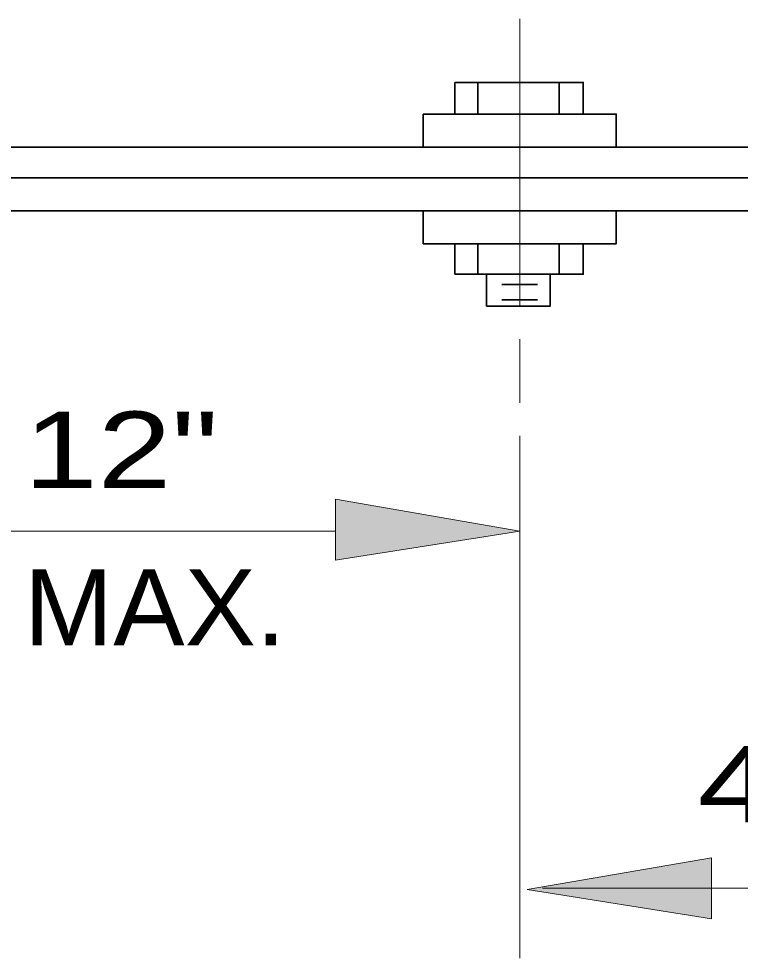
# Model space of a CAD drawing. Extents: x 5332.5 to 5339, y 1824.9 to 1835.1.
# Drawn here: x 5334.646 to 5335.213, y 1826.465 to 1827.204 of the extents above; entities that cross this region are included whole.
import ezdxf

# ---------------------------------------------------------------- set-up
doc = ezdxf.new("R2010")
doc.units = 0
doc.header["$LTSCALE"] = 0.024
for name, color, linetype, lineweight in [('1', 7, 'Continuous', 35), ('10', 7, 'Continuous', 13), ('12', 7, 'Continuous', 53)]:
    doc.layers.add(name, color=color, linetype=linetype, lineweight=lineweight)

msp = doc.modelspace()

# ---------------------------------------------------------------- hatches: boundary and pattern name
at = {"layer": '10'}
for points in [[(5334.895, 1826.778), (5334.895, 1826.826), (5335.04, 1826.801)], [(5334.895, 1826.778), (5334.895, 1826.826), (5335.04, 1826.801)], [(5334.895, 1826.778), (5334.895, 1826.826), (5335.04, 1826.801)], [(5334.895, 1826.778), (5334.895, 1826.826), (5335.04, 1826.801)], [(5334.895, 1826.778), (5334.895, 1826.826), (5335.04, 1826.801)], [(5334.895, 1826.778), (5334.895, 1826.826), (5335.04, 1826.801)], [(5334.895, 1826.778), (5334.895, 1826.826), (5335.04, 1826.801)], [(5334.895, 1826.778), (5334.895, 1826.826), (5335.04, 1826.801)], [(5334.895, 1826.778), (5334.895, 1826.826), (5335.04, 1826.801)], [(5334.895, 1826.778), (5334.895, 1826.826), (5335.04, 1826.801)], [(5334.895, 1826.778), (5334.895, 1826.826), (5335.04, 1826.801)], [(5335.191, 1826.496), (5335.191, 1826.544), (5335.046, 1826.519)]]:
    msp.add_hatch(color=256, dxfattribs=at).paths.add_polyline_path(points)

# ---------------------------------------------------------------- linework, layer by layer
at = {"layer": '1'}
for p, q in [((5334.989, 1827.154), (5335.04, 1827.154)), ((5334.989, 1827.129), (5334.989, 1827.154)), ((5334.989, 1827.154), (5335.04, 1827.154)), ((5334.989, 1827.129), (5334.989, 1827.154)), ((5334.989, 1827.154), (5335.04, 1827.154)), ((5334.989, 1827.129), (5334.989, 1827.154)), ((5334.989, 1827.154), (5335.04, 1827.154)), ((5334.989, 1827.129), (5334.989, 1827.154)), ((5334.989, 1827.154), (5335.04, 1827.154)), ((5334.989, 1827.129), (5334.989, 1827.154)), ((5334.989, 1827.154), (5335.04, 1827.154)), ((5334.989, 1827.129), (5334.989, 1827.154)), ((5334.989, 1827.154), (5335.04, 1827.154)), ((5334.989, 1827.129), (5334.989, 1827.154)), ((5334.989, 1827.154), (5335.04, 1827.154)), ((5334.989, 1827.129), (5334.989, 1827.154)), ((5334.989, 1827.154), (5335.04, 1827.154)), ((5334.989, 1827.129), (5334.989, 1827.154)), ((5334.989, 1827.154), (5335.04, 1827.154)), ((5334.989, 1827.129), (5334.989, 1827.154)), ((5334.989, 1827.154), (5335.04, 1827.154)), ((5334.989, 1827.129), (5334.989, 1827.154)), ((5335.007, 1827.154), (5335.007, 1827.129)), ((5335.007, 1827.154), (5335.007, 1827.129)), ((5335.007, 1827.154), (5335.007, 1827.129)), ((5335.007, 1827.154), (5335.007, 1827.129)), ((5335.007, 1827.154), (5335.007, 1827.129)), ((5335.007, 1827.154), (5335.007, 1827.129)), ((5335.007, 1827.154), (5335.007, 1827.129)), ((5335.007, 1827.154), (5335.007, 1827.129)), ((5335.007, 1827.154), (5335.007, 1827.129)), ((5335.007, 1827.154), (5335.007, 1827.129)), ((5335.007, 1827.154), (5335.007, 1827.129)), ((5335.071, 1827.154), (5335.071, 1827.129)), ((5335.071, 1827.154), (5335.071, 1827.129)), ((5335.071, 1827.154), (5335.071, 1827.129)), ((5335.071, 1827.154), (5335.071, 1827.129)), ((5335.071, 1827.154), (5335.071, 1827.129)), ((5335.071, 1827.154), (5335.071, 1827.129)), ((5335.071, 1827.154), (5335.071, 1827.129)), ((5335.071, 1827.154), (5335.071, 1827.129)), ((5335.071, 1827.154), (5335.071, 1827.129)), ((5335.071, 1827.154), (5335.071, 1827.129)), ((5335.071, 1827.154), (5335.071, 1827.129)), ((5335.071, 1827.154), (5335.071, 1827.129)), ((5335.071, 1827.154), (5335.071, 1827.129)), ((5334.964, 1827.129), (5335.04, 1827.129)), ((5334.964, 1827.103), (5334.964, 1827.129)), ((5334.964, 1827.129), (5335.04, 1827.129)), ((5334.964, 1827.103), (5334.964, 1827.129)), ((5334.964, 1827.129), (5335.04, 1827.129)), ((5334.964, 1827.103), (5334.964, 1827.129)), ((5334.964, 1827.129), (5335.04, 1827.129)), ((5334.964, 1827.103), (5334.964, 1827.129)), ((5334.964, 1827.129), (5335.04, 1827.129)), ((5334.964, 1827.103), (5334.964, 1827.129)), ((5334.964, 1827.129), (5335.04, 1827.129)), ((5334.964, 1827.103), (5334.964, 1827.129)), ((5334.964, 1827.129), (5335.04, 1827.129)), ((5334.964, 1827.103), (5334.964, 1827.129)), ((5334.964, 1827.129), (5335.04, 1827.129)), ((5334.964, 1827.103), (5334.964, 1827.129)), ((5334.964, 1827.129), (5335.04, 1827.129)), ((5334.964, 1827.103), (5334.964, 1827.129)), ((5334.964, 1827.129), (5335.04, 1827.129)), ((5334.964, 1827.103), (5334.964, 1827.129)), ((5334.964, 1827.129), (5335.04, 1827.129)), ((5334.964, 1827.103), (5334.964, 1827.129)), ((5337.53, 1827.103), (5333.857, 1827.103)), ((5334.26, 1827.079), (5335.492, 1827.079)), ((5334.26, 1827.079), (5335.492, 1827.079)), ((5334.26, 1827.079), (5335.492, 1827.079)), ((5334.26, 1827.079), (5335.492, 1827.079)), ((5334.26, 1827.079), (5335.492, 1827.079)), ((5334.26, 1827.079), (5335.492, 1827.079)), ((5334.26, 1827.079), (5335.492, 1827.079)), ((5334.26, 1827.079), (5335.492, 1827.079)), ((5334.26, 1827.079), (5335.492, 1827.079)), ((5334.26, 1827.079), (5335.492, 1827.079)), ((5334.26, 1827.079), (5335.492, 1827.079)), ((5334.26, 1827.079), (5335.492, 1827.079)), ((5334.26, 1827.079), (5335.492, 1827.079)), ((5334.964, 1827.053), (5334.964, 1827.027)), ((5334.964, 1827.053), (5334.964, 1827.027)), ((5334.964, 1827.053), (5334.964, 1827.027)), ((5334.964, 1827.053), (5334.964, 1827.027)), ((5334.964, 1827.053), (5334.964, 1827.027)), ((5334.964, 1827.053), (5334.964, 1827.027)), ((5334.964, 1827.053), (5334.964, 1827.027)), ((5334.964, 1827.053), (5334.964, 1827.027)), ((5334.964, 1827.053), (5334.964, 1827.027)), ((5334.964, 1827.053), (5334.964, 1827.027)), ((5334.964, 1827.053), (5334.964, 1827.027)), ((5334.964, 1827.053), (5334.964, 1827.027)), ((5334.964, 1827.053), (5334.964, 1827.027)), ((5334.964, 1827.027), (5335.04, 1827.027)), ((5334.964, 1827.027), (5335.04, 1827.027)), ((5334.964, 1827.027), (5335.04, 1827.027)), ((5334.964, 1827.027), (5335.04, 1827.027)), ((5334.964, 1827.027), (5335.04, 1827.027)), ((5334.964, 1827.027), (5335.04, 1827.027)), ((5334.964, 1827.027), (5335.04, 1827.027)), ((5334.964, 1827.027), (5335.04, 1827.027)), ((5334.964, 1827.027), (5335.04, 1827.027)), ((5334.964, 1827.027), (5335.04, 1827.027)), ((5334.964, 1827.027), (5335.04, 1827.027)), ((5334.964, 1827.027), (5335.04, 1827.027)), ((5334.964, 1827.027), (5335.04, 1827.027)), ((5334.989, 1827.027), (5334.989, 1827.003)), ((5334.989, 1827.027), (5334.989, 1827.003)), ((5334.989, 1827.027), (5334.989, 1827.003)), ((5334.989, 1827.027), (5334.989, 1827.003)), ((5334.989, 1827.027), (5334.989, 1827.003)), ((5334.989, 1827.027), (5334.989, 1827.003)), ((5334.989, 1827.027), (5334.989, 1827.003)), ((5334.989, 1827.027), (5334.989, 1827.003)), ((5334.989, 1827.027), (5334.989, 1827.003)), ((5334.989, 1827.027), (5334.989, 1827.003)), ((5334.989, 1827.027), (5334.989, 1827.003)), ((5334.989, 1827.027), (5334.989, 1827.003)), ((5334.989, 1827.027), (5334.989, 1827.003)), ((5335.007, 1827.003), (5335.007, 1827.027)), ((5335.007, 1827.003), (5335.007, 1827.027)), ((5335.007, 1827.003), (5335.007, 1827.027)), ((5335.007, 1827.003), (5335.007, 1827.027)), ((5335.007, 1827.003), (5335.007, 1827.027)), ((5335.007, 1827.003), (5335.007, 1827.027)), ((5335.007, 1827.003), (5335.007, 1827.027)), ((5335.007, 1827.003), (5335.007, 1827.027)), ((5335.007, 1827.003), (5335.007, 1827.027)), ((5335.007, 1827.003), (5335.007, 1827.027)), ((5335.007, 1827.003), (5335.007, 1827.027)), ((5335.007, 1827.003), (5335.007, 1827.027)), ((5335.007, 1827.003), (5335.007, 1827.027)), ((5335.071, 1827.003), (5335.071, 1827.027)), ((5335.071, 1827.003), (5335.071, 1827.027)), ((5335.071, 1827.003), (5335.071, 1827.027)), ((5335.071, 1827.003), (5335.071, 1827.027)), ((5335.071, 1827.003), (5335.071, 1827.027)), ((5335.071, 1827.003), (5335.071, 1827.027)), ((5335.071, 1827.003), (5335.071, 1827.027)), ((5335.071, 1827.003), (5335.071, 1827.027)), ((5335.071, 1827.003), (5335.071, 1827.027)), ((5335.071, 1827.003), (5335.071, 1827.027)), ((5335.071, 1827.003), (5335.071, 1827.027)), ((5335.071, 1827.003), (5335.071, 1827.027)), ((5335.071, 1827.003), (5335.071, 1827.027)), ((5334.989, 1827.003), (5335.04, 1827.003)), ((5334.989, 1827.003), (5335.04, 1827.003)), ((5334.989, 1827.003), (5335.04, 1827.003)), ((5334.989, 1827.003), (5335.04, 1827.003)), ((5334.989, 1827.003), (5335.04, 1827.003)), ((5334.989, 1827.003), (5335.04, 1827.003)), ((5334.989, 1827.003), (5335.04, 1827.003)), ((5334.989, 1827.003), (5335.04, 1827.003)), ((5334.989, 1827.003), (5335.04, 1827.003)), ((5334.989, 1827.003), (5335.04, 1827.003)), ((5334.989, 1827.003), (5335.04, 1827.003)), ((5334.989, 1827.003), (5335.04, 1827.003)), ((5334.989, 1827.003), (5335.04, 1827.003)), ((5335.014, 1827.003), (5335.014, 1826.978)), ((5335.014, 1827.003), (5335.014, 1826.978)), ((5335.014, 1827.003), (5335.014, 1826.978)), ((5335.014, 1827.003), (5335.014, 1826.978)), ((5335.014, 1827.003), (5335.014, 1826.978)), ((5335.014, 1827.003), (5335.014, 1826.978)), ((5335.014, 1827.003), (5335.014, 1826.978)), ((5335.014, 1827.003), (5335.014, 1826.978)), ((5335.014, 1827.003), (5335.014, 1826.978)), ((5335.014, 1827.003), (5335.014, 1826.978)), ((5335.014, 1827.003), (5335.014, 1826.978)), ((5335.014, 1827.003), (5335.014, 1826.978)), ((5335.014, 1827.003), (5335.014, 1826.978)), ((5335.026, 1826.995), (5335.054, 1826.995)), ((5335.026, 1826.995), (5335.054, 1826.995)), ((5335.026, 1826.995), (5335.054, 1826.995)), ((5335.026, 1826.995), (5335.054, 1826.995)), ((5335.026, 1826.995), (5335.054, 1826.995)), ((5335.026, 1826.995), (5335.054, 1826.995)), ((5335.026, 1826.995), (5335.054, 1826.995)), ((5335.026, 1826.995), (5335.054, 1826.995)), ((5335.026, 1826.995), (5335.054, 1826.995)), ((5335.026, 1826.995), (5335.054, 1826.995)), ((5335.026, 1826.995), (5335.054, 1826.995)), ((5335.026, 1826.995), (5335.054, 1826.995)), ((5335.026, 1826.995), (5335.054, 1826.995)), ((5335.014, 1826.978), (5335.04, 1826.978)), ((5335.014, 1826.978), (5335.04, 1826.978)), ((5335.014, 1826.978), (5335.04, 1826.978)), ((5335.014, 1826.978), (5335.04, 1826.978)), ((5335.014, 1826.978), (5335.04, 1826.978)), ((5335.014, 1826.978), (5335.04, 1826.978)), ((5335.014, 1826.978), (5335.04, 1826.978)), ((5335.014, 1826.978), (5335.04, 1826.978)), ((5335.014, 1826.978), (5335.04, 1826.978)), ((5335.014, 1826.978), (5335.04, 1826.978)), ((5335.014, 1826.978), (5335.04, 1826.978)), ((5335.014, 1826.978), (5335.04, 1826.978)), ((5335.014, 1826.978), (5335.04, 1826.978)), ((5335.026, 1826.983), (5335.054, 1826.983)), ((5335.026, 1826.983), (5335.054, 1826.983)), ((5335.026, 1826.983), (5335.054, 1826.983)), ((5335.026, 1826.983), (5335.054, 1826.983)), ((5335.026, 1826.983), (5335.054, 1826.983)), ((5335.026, 1826.983), (5335.054, 1826.983)), ((5335.026, 1826.983), (5335.054, 1826.983)), ((5335.026, 1826.983), (5335.054, 1826.983)), ((5335.026, 1826.983), (5335.054, 1826.983)), ((5335.026, 1826.983), (5335.054, 1826.983)), ((5335.026, 1826.983), (5335.054, 1826.983)), ((5335.026, 1826.983), (5335.054, 1826.983)), ((5335.026, 1826.983), (5335.054, 1826.983))]:
    msp.add_line(p, q, dxfattribs=at)
for points in [[(5335.09, 1827.129), (5335.09, 1827.154), (5335.04, 1827.154)], [(5335.09, 1827.129), (5335.09, 1827.154), (5335.04, 1827.154)], [(5335.09, 1827.129), (5335.09, 1827.154), (5335.04, 1827.154)], [(5335.09, 1827.129), (5335.09, 1827.154), (5335.04, 1827.154)], [(5335.09, 1827.129), (5335.09, 1827.154), (5335.04, 1827.154)], [(5335.09, 1827.129), (5335.09, 1827.154), (5335.04, 1827.154)], [(5335.09, 1827.129), (5335.09, 1827.154), (5335.04, 1827.154)], [(5335.09, 1827.129), (5335.09, 1827.154), (5335.04, 1827.154)], [(5335.09, 1827.129), (5335.09, 1827.154), (5335.04, 1827.154)], [(5335.09, 1827.129), (5335.09, 1827.154), (5335.04, 1827.154)], [(5335.09, 1827.129), (5335.09, 1827.154), (5335.04, 1827.154)], [(5335.09, 1827.129), (5335.09, 1827.154), (5335.04, 1827.154)], [(5335.09, 1827.129), (5335.09, 1827.154), (5335.04, 1827.154)], [(5335.116, 1827.103), (5335.116, 1827.129), (5335.04, 1827.129)], [(5335.116, 1827.103), (5335.116, 1827.129), (5335.04, 1827.129)], [(5335.116, 1827.103), (5335.116, 1827.129), (5335.04, 1827.129)], [(5335.116, 1827.103), (5335.116, 1827.129), (5335.04, 1827.129)], [(5335.116, 1827.103), (5335.116, 1827.129), (5335.04, 1827.129)], [(5335.116, 1827.103), (5335.116, 1827.129), (5335.04, 1827.129)], [(5335.116, 1827.103), (5335.116, 1827.129), (5335.04, 1827.129)], [(5335.116, 1827.103), (5335.116, 1827.129), (5335.04, 1827.129)], [(5335.116, 1827.103), (5335.116, 1827.129), (5335.04, 1827.129)], [(5335.116, 1827.103), (5335.116, 1827.129), (5335.04, 1827.129)], [(5335.116, 1827.103), (5335.116, 1827.129), (5335.04, 1827.129)], [(5335.116, 1827.103), (5335.116, 1827.129), (5335.04, 1827.129)], [(5335.116, 1827.103), (5335.116, 1827.129), (5335.04, 1827.129)], [(5337.53, 1827.103), (5333.857, 1827.103), (5333.857, 1827.079), (5334.26, 1827.079)], [(5337.53, 1827.103), (5333.857, 1827.103), (5333.857, 1827.079), (5334.26, 1827.079)], [(5337.53, 1827.103), (5333.857, 1827.103), (5333.857, 1827.079), (5334.26, 1827.079)], [(5337.53, 1827.103), (5333.857, 1827.103), (5333.857, 1827.079), (5334.26, 1827.079)], [(5337.53, 1827.103), (5333.857, 1827.103), (5333.857, 1827.079), (5334.26, 1827.079)], [(5337.53, 1827.103), (5333.857, 1827.103), (5333.857, 1827.079), (5334.26, 1827.079)], [(5337.53, 1827.103), (5333.857, 1827.103), (5333.857, 1827.079), (5334.26, 1827.079)], [(5337.53, 1827.103), (5333.857, 1827.103), (5333.857, 1827.079), (5334.26, 1827.079)], [(5337.53, 1827.103), (5333.857, 1827.103), (5333.857, 1827.079), (5334.26, 1827.079)], [(5337.53, 1827.103), (5333.857, 1827.103), (5333.857, 1827.079), (5334.26, 1827.079)], [(5337.53, 1827.103), (5333.857, 1827.103), (5333.857, 1827.079), (5334.26, 1827.079)], [(5337.53, 1827.103), (5333.857, 1827.103), (5333.857, 1827.079), (5334.26, 1827.079)], [(5337.53, 1827.103), (5333.857, 1827.103), (5333.857, 1827.079), (5334.26, 1827.079)], [(5334.26, 1827.079), (5334.26, 1827.053), (5335.465, 1827.053)], [(5334.26, 1827.079), (5334.26, 1827.053), (5335.465, 1827.053)], [(5334.26, 1827.079), (5334.26, 1827.053), (5335.465, 1827.053)], [(5334.26, 1827.079), (5334.26, 1827.053), (5335.465, 1827.053)], [(5334.26, 1827.079), (5334.26, 1827.053), (5335.465, 1827.053)], [(5334.26, 1827.079), (5334.26, 1827.053), (5335.465, 1827.053)], [(5334.26, 1827.079), (5334.26, 1827.053), (5335.465, 1827.053)], [(5334.26, 1827.079), (5334.26, 1827.053), (5335.465, 1827.053)], [(5334.26, 1827.079), (5334.26, 1827.053), (5335.465, 1827.053)], [(5334.26, 1827.079), (5334.26, 1827.053), (5335.465, 1827.053)], [(5334.26, 1827.079), (5334.26, 1827.053), (5335.465, 1827.053)], [(5334.26, 1827.079), (5334.26, 1827.053), (5335.465, 1827.053)], [(5334.26, 1827.079), (5334.26, 1827.053), (5335.465, 1827.053)], [(5335.116, 1827.053), (5335.116, 1827.027), (5335.04, 1827.027)], [(5335.116, 1827.053), (5335.116, 1827.027), (5335.04, 1827.027)], [(5335.116, 1827.053), (5335.116, 1827.027), (5335.04, 1827.027)], [(5335.116, 1827.053), (5335.116, 1827.027), (5335.04, 1827.027)], [(5335.116, 1827.053), (5335.116, 1827.027), (5335.04, 1827.027)], [(5335.116, 1827.053), (5335.116, 1827.027), (5335.04, 1827.027)], [(5335.116, 1827.053), (5335.116, 1827.027), (5335.04, 1827.027)], [(5335.116, 1827.053), (5335.116, 1827.027), (5335.04, 1827.027)], [(5335.116, 1827.053), (5335.116, 1827.027), (5335.04, 1827.027)], [(5335.116, 1827.053), (5335.116, 1827.027), (5335.04, 1827.027)], [(5335.116, 1827.053), (5335.116, 1827.027), (5335.04, 1827.027)], [(5335.116, 1827.053), (5335.116, 1827.027), (5335.04, 1827.027)], [(5335.116, 1827.053), (5335.116, 1827.027), (5335.04, 1827.027)], [(5335.09, 1827.027), (5335.09, 1827.003), (5335.04, 1827.003)], [(5335.09, 1827.027), (5335.09, 1827.003), (5335.04, 1827.003)], [(5335.09, 1827.027), (5335.09, 1827.003), (5335.04, 1827.003)], [(5335.09, 1827.027), (5335.09, 1827.003), (5335.04, 1827.003)], [(5335.09, 1827.027), (5335.09, 1827.003), (5335.04, 1827.003)], [(5335.09, 1827.027), (5335.09, 1827.003), (5335.04, 1827.003)], [(5335.09, 1827.027), (5335.09, 1827.003), (5335.04, 1827.003)], [(5335.09, 1827.027), (5335.09, 1827.003), (5335.04, 1827.003)], [(5335.09, 1827.027), (5335.09, 1827.003), (5335.04, 1827.003)], [(5335.09, 1827.027), (5335.09, 1827.003), (5335.04, 1827.003)], [(5335.09, 1827.027), (5335.09, 1827.003), (5335.04, 1827.003)], [(5335.09, 1827.027), (5335.09, 1827.003), (5335.04, 1827.003)], [(5335.09, 1827.027), (5335.09, 1827.003), (5335.04, 1827.003)], [(5335.064, 1827.003), (5335.064, 1826.978), (5335.04, 1826.978)], [(5335.064, 1827.003), (5335.064, 1826.978), (5335.04, 1826.978)], [(5335.064, 1827.003), (5335.064, 1826.978), (5335.04, 1826.978)], [(5335.064, 1827.003), (5335.064, 1826.978), (5335.04, 1826.978)], [(5335.064, 1827.003), (5335.064, 1826.978), (5335.04, 1826.978)], [(5335.064, 1827.003), (5335.064, 1826.978), (5335.04, 1826.978)], [(5335.064, 1827.003), (5335.064, 1826.978), (5335.04, 1826.978)], [(5335.064, 1827.003), (5335.064, 1826.978), (5335.04, 1826.978)], [(5335.064, 1827.003), (5335.064, 1826.978), (5335.04, 1826.978)], [(5335.064, 1827.003), (5335.064, 1826.978), (5335.04, 1826.978)], [(5335.064, 1827.003), (5335.064, 1826.978), (5335.04, 1826.978)], [(5335.064, 1827.003), (5335.064, 1826.978), (5335.04, 1826.978)], [(5335.064, 1827.003), (5335.064, 1826.978), (5335.04, 1826.978)]]:
    msp.add_lwpolyline(points, dxfattribs=at)
at = {"layer": '10'}
for p, q in [((5335.04, 1827.204), (5335.04, 1826.978)), ((5335.04, 1827.204), (5335.04, 1826.978)), ((5335.04, 1827.204), (5335.04, 1826.978)), ((5335.04, 1827.204), (5335.04, 1826.978)), ((5335.04, 1827.204), (5335.04, 1826.978)), ((5335.04, 1827.204), (5335.04, 1826.978)), ((5335.04, 1827.204), (5335.04, 1826.978)), ((5335.04, 1827.204), (5335.04, 1826.978)), ((5335.04, 1827.204), (5335.04, 1826.978)), ((5335.04, 1827.204), (5335.04, 1826.978)), ((5335.04, 1827.204), (5335.04, 1826.978)), ((5335.04, 1826.952), (5335.04, 1826.902)), ((5335.04, 1826.952), (5335.04, 1826.902)), ((5335.04, 1826.952), (5335.04, 1826.902)), ((5335.04, 1826.952), (5335.04, 1826.902)), ((5335.04, 1826.952), (5335.04, 1826.902)), ((5335.04, 1826.952), (5335.04, 1826.902)), ((5335.04, 1826.952), (5335.04, 1826.902)), ((5335.04, 1826.952), (5335.04, 1826.902)), ((5335.04, 1826.952), (5335.04, 1826.902)), ((5335.04, 1826.952), (5335.04, 1826.902)), ((5335.04, 1826.952), (5335.04, 1826.902)), ((5335.04, 1826.876), (5335.04, 1826.776)), ((5335.04, 1826.876), (5335.04, 1826.465)), ((5335.04, 1826.876), (5335.04, 1826.776)), ((5335.04, 1826.876), (5335.04, 1826.776)), ((5335.04, 1826.876), (5335.04, 1826.776)), ((5335.04, 1826.876), (5335.04, 1826.776)), ((5335.04, 1826.876), (5335.04, 1826.776)), ((5335.04, 1826.876), (5335.04, 1826.776)), ((5335.04, 1826.876), (5335.04, 1826.776)), ((5335.04, 1826.876), (5335.04, 1826.776)), ((5335.04, 1826.876), (5335.04, 1826.776)), ((5334.895, 1826.801), (5334.511, 1826.801)), ((5334.895, 1826.801), (5334.511, 1826.801)), ((5334.895, 1826.801), (5334.511, 1826.801)), ((5334.895, 1826.801), (5334.511, 1826.801)), ((5334.895, 1826.801), (5334.511, 1826.801)), ((5334.895, 1826.801), (5334.511, 1826.801)), ((5334.895, 1826.801), (5334.511, 1826.801)), ((5334.895, 1826.801), (5334.511, 1826.801)), ((5334.895, 1826.801), (5334.511, 1826.801)), ((5334.895, 1826.801), (5334.511, 1826.801)), ((5334.895, 1826.801), (5334.511, 1826.801)), ((5335.678, 1826.52), (5335.058, 1826.52))]:
    msp.add_line(p, q, dxfattribs=at)
for points in [[(5334.895, 1826.778), (5334.895, 1826.826), (5335.04, 1826.801)], [(5334.895, 1826.778), (5334.895, 1826.826), (5335.04, 1826.801)], [(5334.895, 1826.778), (5334.895, 1826.826), (5335.04, 1826.801)], [(5334.895, 1826.778), (5334.895, 1826.826), (5335.04, 1826.801)], [(5334.895, 1826.778), (5334.895, 1826.826), (5335.04, 1826.801)], [(5334.895, 1826.778), (5334.895, 1826.826), (5335.04, 1826.801)], [(5334.895, 1826.778), (5334.895, 1826.826), (5335.04, 1826.801)], [(5334.895, 1826.778), (5334.895, 1826.826), (5335.04, 1826.801)], [(5334.895, 1826.778), (5334.895, 1826.826), (5335.04, 1826.801)], [(5334.895, 1826.778), (5334.895, 1826.826), (5335.04, 1826.801)], [(5334.895, 1826.778), (5334.895, 1826.826), (5335.04, 1826.801)], [(5335.191, 1826.496), (5335.191, 1826.544), (5335.046, 1826.519)]]:
    msp.add_lwpolyline(points, close=True, dxfattribs=at)

# ---------------------------------------------------------------- texts
at = {"layer": '12'}
for s, width, p in [('12"', 1.3, (5334.65, 1826.835)), ('MAX.', 1.05, (5334.65, 1826.711)), ('4" TYP.', 1.35, (5335.18, 1826.572))]:
    msp.add_text(s, height=0.06, dxfattribs=dict(at, width=width)).set_placement(p)

doc.saveas('drawing.dxf')
